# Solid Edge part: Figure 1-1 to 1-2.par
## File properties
Author: CADCIM
Template: normal.par
Last saved by: Ashutosh-CADCIM
Revision: 17
Application: Solid Edge
Accuracy: 0.99
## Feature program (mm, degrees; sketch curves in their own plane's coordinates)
sketch for "unnamed Protrusion 1" plane through (0, 0, 0) normal (0, 0, 1) x-axis (1, 0, 0)
  line (-63.0032, 49) -> (-56, -71)
  line (-56, -71) -> (56, -71)
  line (56, -71) -> (63.0032, 49)
  line (63.0032, 49) -> (0, 54)
  line (0, 54) -> (-63.0032, 49)
  dimension (linear) = 56
  dimension (linear) = 56
extrude "unnamed Protrusion 1" add finite 4 along +normal
fillet "Round_1" radius 15
sketch for "ExtrudedProtrusion_3" plane through (0, -8.5, 0) normal (0, 0, -1) x-axis (-1, 0, 0)
extrude "ExtrudedProtrusion_3" add finite 12 along -normal
pattern "unnamed Pattern 1" of "ExtrudedProtrusion_3"
pattern "unnamed Pattern 2"
sketch for "unnamed Protrusion 2" plane through (-1.0316, 2.3101, 4) normal (0, 0, 1) x-axis (-1, 0, 0)
extrude "unnamed Protrusion 2" add finite 5 along +normal
sketch for "Hole_22" plane through (40.9331, -54.9887, 12) normal (0, 0, 1) x-axis (1, 0, 0)
  hole centre (-0.4331, -0.0113) bore radius 4.5
hole "Hole_22" diameter 9 through  CounterBoreDepth = 5 mm
pattern "unnamed Pattern 3" of "Hole_22"
hole "unnamed Hole 1" through
hole "unnamed Hole 2" through
hole "unnamed Hole 3" through
sketch for "Hole_29" plane through (-1.0316, -6.1899, 9) normal (0, 0, 1) x-axis (1, 0, 0)
  hole centre (0, 0) bore radius 11
hole "Hole_29" diameter 22 through
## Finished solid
Body 1: solid body, 34 faces, 55 edges, 18 vertices.
  Faces by surface: cylinder 18, plane 16
  Edges by curve: circle 36, line 19
Bounding box of the edges (mm): 124.346 x 125.000 x 12.000, from (-62.1729, -71, 0) to (62.1729, 54, 12).
Cylindrical faces by radius (mm): R4.5 x4, R7.5 x4, R10.7006 x4, R11 x1, R15 x4, R20 x1
Planar faces by outward normal: +z 10, -y 1, -z 1, oblique 4
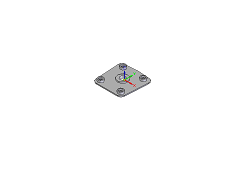
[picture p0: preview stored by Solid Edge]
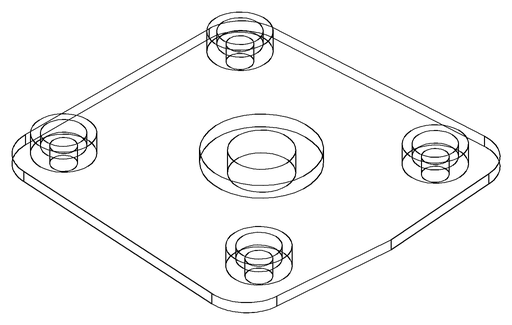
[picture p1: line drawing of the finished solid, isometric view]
